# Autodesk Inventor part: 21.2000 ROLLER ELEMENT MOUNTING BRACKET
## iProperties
Created: 2007-05
Part Number: 21.2000 ROLLER ELEMENT MOUNTING BRACKET
Material: Steel
Document SubType Name: Modeling
Designer: Andy Moles
Density: 7.85 g/cm^3
Mass: 60.2927 g
Surface Area: 59.3613 cm^2
Volume: 7.68059 cm^3
Author: Andy Moles
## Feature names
1. Base1
2. Extrusion1
